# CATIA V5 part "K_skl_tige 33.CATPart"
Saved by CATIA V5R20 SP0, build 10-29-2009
Part number: skl_tige 33
Publications: "longueur tige", "longueur axe pivot", "liaison 24/33 sur 33", "droite appui verin droite", "Droite.1", "Droite.3", "Plan.-55"
Bounding box of the stored display mesh (mm): x -205 to -55, y 466.656 to 975, z 0 to 209.968
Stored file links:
  G:\Khaled_CFAO_2011\SIL\SIL_GR2\mdardier\Khaled\CAD_ThinkMOTION\K_skl_tige 33.CATPart
  G:\Khaled_CFAO_2011\SIL\SIL_GR2\mdardier\Khaled\CAD_ThinkMOTION\K_skl_ass_tandem.CATProduct
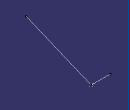
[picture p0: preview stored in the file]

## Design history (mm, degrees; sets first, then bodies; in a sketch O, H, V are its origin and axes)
External parameters (linked from other documents)
  `External.longueur tige` = 550 mm
  `External.longueur axe pivot` = 150 mm
Set1
  Point1 "liaison 24/33 sur 33": linked copy from another document
  Line1 "droite appui verin droite": linked copy from another document
  Plane1 "Plan.-55": linked copy from another document
Set2
  Line2: type PtDir, RefPoint Point1, Direction Line1, Start 0, End 550 {= `External.longueur tige`}
  Line3: type Normal, RefPoint Point1, RefSkin Plane1, Start 0, End 150 {= `External.longueur axe pivot`}
Body1 (main body)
